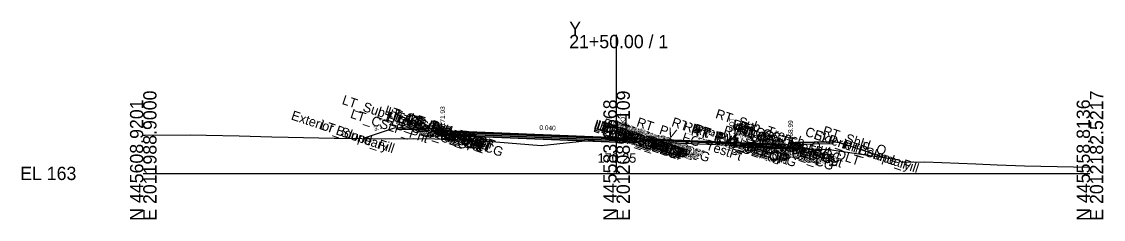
# Model space of a CAD drawing. Extents: x -26 to 3203, y -10 to 9532.
# Drawn here: x 974.3 to 1202.8, y 5490.3 to 5532 of the extents above; entities that cross this region are included whole.
import ezdxf

# ---------------------------------------------------------------- set-up
doc = ezdxf.new("R2010")
doc.units = 0
for name, color, linetype in [('Default', 7, 'Continuous'), ('Exist Cross Section Cell', 7, 'Continuous'), ('Exist XS Center Line Elevation Label', 7, 'Continuous'), ('Exist XS Ground Line', 7, 'Continuous'), ('Prop CMT Conc Surface', 7, 'Continuous'), ('Prop CMT Concrete Structures', 7, 'Continuous'), ('Prop CMT Pvmt Course 1', 7, 'Continuous'), ('Prop CMT Pvmt Course 1 CG', 7, 'Continuous'), ('Prop CMT Pvmt Course 1 Wedge', 7, 'Continuous'), ('Prop CMT Pvmt Course 2', 7, 'Continuous'), ('Prop CMT Pvmt Course 2 Wedge', 7, 'Continuous'), ('Prop CMT Pvmt Course 3', 7, 'Continuous'), ('Prop CMT Pvmt Surface', 7, 'Continuous'), ('Prop CMT Pvmt Wedge Surface 1', 7, 'Continuous'), ('Prop CMT Pvmt Wedge Surface 2', 7, 'Continuous'), ('Prop CMT Pvmt Wedge Surface 3', 7, 'Continuous'), ('Prop CMT Slope Grass', 7, 'Continuous'), ('Prop CMT Subgrade Earthwork', 7, 'Continuous'), ('Prop XS Hydro Elevations', 7, 'Continuous'), ('Prop XS Label Text', 7, 'Continuous'), ('Prop XS SE Text', 7, 'Continuous'), ('Prop XS Side Slope Text', 7, 'Continuous'), ('Scratch_Level_0', 7, 'Continuous')]:
    doc.layers.add(name, color=color, linetype=linetype)

msp = doc.modelspace()

# ---------------------------------------------------------------- linework, layer by layer
at = {"layer": 'Exist Cross Section Cell'}
for p, q in [((1100, 5500), (1100, 5529.22)), ((1000, 5500), (1100, 5500)), ((1100, 5500), (1200, 5500))]:
    msp.add_line(p, q, dxfattribs=at)
at = {"layer": 'Exist XS Ground Line'}
msp.add_lwpolyline([(1000, 5508.07), (1000.38, 5508.07), (1009.93, 5508.16), (1013.26, 5508.09), (1020.26, 5507.92), (1027.2, 5507.72), (1030.59, 5507.63), (1040.3, 5507.46), (1041.13, 5507.45), (1051.25, 5507.26), (1057.2, 5507.34), (1061.58, 5507.26), (1065.87, 5507.05), (1074.48, 5506.64), (1084.06, 5505.91), (1095.34, 5507.05), (1100, 5507.25), (1100.5, 5507.27), (1100.92, 5507.26), (1101.44, 5507.25), (1101.95, 5507.23), (1104.24, 5507.15), (1105.29, 5507.11), (1106.54, 5507.07), (1106.99, 5507.06), (1109.12, 5506.97), (1110.46, 5506.91), (1111.69, 5506.85), (1112.71, 5506.81), (1113.33, 5506.79), (1114.24, 5506.74), (1115.2, 5506.71), (1116.5, 5506.66), (1116.83, 5506.64), (1117.39, 5506.62), (1119.4, 5506.53), (1120.87, 5506.45), (1121.99, 5506.4), (1124.64, 5506.26), (1124.95, 5506.25), (1126.13, 5506.17), (1132.72, 5505.52), (1136.51, 5505.3), (1145.01, 5505.01), (1159.73, 5502.89), (1160.16, 5502.4), (1165.09, 5502.43), (1175.9, 5502.03), (1180.39, 5501.84), (1186.15, 5501.57), (1200, 5501.34)], dxfattribs=at)
at = {"layer": 'Prop CMT Conc Surface'}
for points in [[(1058.75, 5509.52), (1053.75, 5509.62)], [(1063.25, 5508.93), (1063.25, 5509.43), (1062.75, 5509.43)], [(1065.25, 5508.93), (1063.25, 5508.93)], [(1134.75, 5506.15), (1136.75, 5505.99)], [(1136.75, 5505.99), (1136.75, 5506.49), (1137.25, 5506.49)]]:
    msp.add_lwpolyline(points, dxfattribs=at)
at = {"layer": 'Prop CMT Concrete Structures'}
for points in [[(1053.75, 5509.28), (1053.75, 5509.62)], [(1053.75, 5509.62), (1058.75, 5509.52)], [(1058.75, 5509.18), (1053.75, 5509.28)], [(1058.75, 5509.52), (1058.75, 5509.18)], [(1065.25, 5508.93), (1063.25, 5508.93), (1063.25, 5509.43), (1062.75, 5509.43)], [(1062.75, 5509.43), (1062.75, 5508.44), (1065.25, 5508.34)], [(1065.25, 5508.34), (1065.25, 5508.93)], [(1108.5, 5507.2), (1108.49, 5507.36), (1107.74, 5507.61), (1107, 5507.75), (1106.26, 5507.73), (1105.51, 5507.48), (1105.5, 5507.32)], [(1105.5, 5507.32), (1108.5, 5507.2)], [(1134.75, 5506.15), (1136.75, 5505.99), (1136.75, 5506.49), (1137.25, 5506.49)], [(1137.25, 5506.49), (1137.25, 5505.46), (1134.75, 5505.56)], [(1134.75, 5505.56), (1134.75, 5506.15)], [(1145.75, 5506.67), (1137.75, 5506.51)], [(1137.75, 5506.51), (1137.75, 5506.17)], [(1137.75, 5506.17), (1145.75, 5506.33)], [(1145.75, 5506.33), (1145.75, 5506.67)]]:
    msp.add_lwpolyline(points, dxfattribs=at)
at = {"layer": 'Prop CMT Pvmt Course 1'}
for points in [[(1105.5, 5507.32), (1065.25, 5508.93)], [(1065.25, 5508.93), (1065.25, 5508.68)], [(1065.25, 5508.68), (1101.95, 5507.21)], [(1101.95, 5507.21), (1101.95, 5507.46)], [(1101.95, 5507.21), (1101.95, 5507.46)], [(1105.5, 5507.32), (1108.5, 5507.2)], [(1105.5, 5507.07), (1105.5, 5507.32)], [(1105.5, 5507.07), (1105.5, 5507.32)], [(1108.5, 5507.2), (1108.5, 5506.95)], [(1108.5, 5507.2), (1134.75, 5506.15)], [(1108.5, 5506.95), (1108.5, 5507.2)], [(1124.95, 5506.41), (1108.5, 5507.07)], [(1108.5, 5507.07), (1108.5, 5506.95), (1108.5, 5506.95)], [(1124.95, 5506.29), (1124.95, 5506.41)], [(1134.75, 5505.9), (1126.13, 5506.24)], [(1134.75, 5506.15), (1134.75, 5505.9)]]:
    msp.add_lwpolyline(points, dxfattribs=at)
for points in [[(1101.95, 5507.21), (1101.95, 5507.33), (1101.95, 5507.33), (1101.95, 5507.21)], [(1105.5, 5507.07), (1105.5, 5507.19), (1105.5, 5507.19), (1105.5, 5507.07)]]:
    msp.add_lwpolyline(points, close=True, dxfattribs=at)
at = {"layer": 'Prop CMT Pvmt Course 1 CG'}
for points in [[(1065.25, 5508.34), (1062.25, 5508.46), (1061.93, 5508.14)], [(1061.93, 5508.14), (1065.25, 5508.01)], [(1065.25, 5508.01), (1065.25, 5508.34)], [(1134.75, 5505.56), (1137.75, 5505.44), (1138.1, 5505.1)], [(1134.75, 5505.23), (1134.75, 5505.56)], [(1138.1, 5505.1), (1134.75, 5505.23)]]:
    msp.add_lwpolyline(points, dxfattribs=at)
at = {"layer": 'Prop CMT Pvmt Course 1 Wedge'}
for points in [[(1108.5, 5506.99), (1108.5, 5507.07)], [(1108.5, 5507.07), (1109.12, 5507.05), (1110.46, 5506.99), (1111.69, 5506.94), (1112.71, 5506.9), (1113.33, 5506.88), (1114.06, 5506.85), (1114.24, 5506.84), (1115.2, 5506.8), (1116.5, 5506.75), (1116.83, 5506.74), (1117.39, 5506.71), (1119.4, 5506.63), (1120.87, 5506.58), (1121.99, 5506.53), (1124.36, 5506.44), (1124.58, 5506.43), (1124.64, 5506.43), (1124.95, 5506.41)], [(1124.95, 5506.29), (1124.64, 5506.3), (1124.58, 5506.3), (1124.36, 5506.31), (1121.99, 5506.41), (1121.11, 5506.44), (1120.87, 5506.45), (1119.4, 5506.53), (1117.39, 5506.62), (1116.83, 5506.64), (1116.5, 5506.66), (1115.2, 5506.71), (1114.24, 5506.74), (1114.06, 5506.75), (1113.33, 5506.79), (1112.71, 5506.81), (1111.69, 5506.85), (1110.46, 5506.91), (1109.12, 5506.97), (1108.5, 5506.99)], [(1124.95, 5506.41), (1124.95, 5506.29), (1124.95, 5506.29)]]:
    msp.add_lwpolyline(points, dxfattribs=at)
at = {"layer": 'Prop CMT Pvmt Course 2'}
for points in [[(1101.95, 5507.21), (1065.25, 5508.68)], [(1065.25, 5508.68), (1065.25, 5508.34)], [(1065.25, 5508.34), (1101.95, 5506.87)], [(1101.95, 5506.87), (1101.95, 5507.21)], [(1101.95, 5506.87), (1101.95, 5507.21)], [(1124.95, 5505.95), (1124.95, 5506.29)], [(1124.95, 5506.29), (1134.75, 5505.9)], [(1134.75, 5505.56), (1126.13, 5505.91)], [(1134.75, 5505.9), (1134.75, 5505.56)]]:
    msp.add_lwpolyline(points, dxfattribs=at)
at = {"layer": 'Prop CMT Pvmt Course 2 Wedge'}
for points in [[(1126.13, 5506.17), (1125.97, 5506.18), (1125.07, 5506.24), (1124.95, 5506.25), (1124.64, 5506.26), (1124.58, 5506.26), (1124.36, 5506.27), (1121.99, 5506.4), (1121.11, 5506.44)], [(1121.11, 5506.44), (1121.99, 5506.41)], [(1121.99, 5506.41), (1124.36, 5506.31), (1124.58, 5506.3), (1124.64, 5506.3), (1124.95, 5506.29)], [(1124.95, 5506.29), (1124.95, 5506.22), (1124.95, 5506.22)]]:
    msp.add_lwpolyline(points, dxfattribs=at)
at = {"layer": 'Prop CMT Pvmt Course 3'}
for points in [[(1101.95, 5506.87), (1065.25, 5508.34)], [(1065.25, 5508.34), (1065.25, 5508.01)], [(1065.25, 5508.01), (1101.95, 5506.54)], [(1101.95, 5506.54), (1101.95, 5506.87)], [(1101.95, 5506.54), (1101.95, 5506.87)], [(1124.95, 5505.95), (1134.75, 5505.56)], [(1124.95, 5505.62), (1124.95, 5505.95)], [(1134.75, 5505.23), (1124.95, 5505.62)], [(1134.75, 5505.56), (1134.75, 5505.23)]]:
    msp.add_lwpolyline(points, dxfattribs=at)
at = {"layer": 'Prop CMT Pvmt Surface'}
for points in [[(1105.5, 5507.32), (1065.25, 5508.93)], [(1105.5, 5507.32), (1108.5, 5507.2)], [(1108.5, 5507.2), (1134.75, 5506.15)]]:
    msp.add_lwpolyline(points, dxfattribs=at)
at = {"layer": 'Prop CMT Pvmt Wedge Surface 1'}
for points in [[(1108.5, 5507.2), (1108.5, 5506.95), (1108.5, 5506.95), (1108.5, 5507.07)], [(1108.5, 5507.07), (1124.95, 5506.41)], [(1124.95, 5506.41), (1124.95, 5506.29)], [(1126.13, 5506.24), (1134.75, 5505.9)], [(1134.75, 5505.9), (1134.75, 5506.15)]]:
    msp.add_lwpolyline(points, dxfattribs=at)
at = {"layer": 'Prop CMT Pvmt Wedge Surface 2'}
for points in [[(1101.95, 5507.21), (1134.75, 5505.9)], [(1108.5, 5507.2), (1108.5, 5506.95)], [(1134.75, 5505.9), (1134.75, 5506.15)]]:
    msp.add_lwpolyline(points, dxfattribs=at)
at = {"layer": 'Prop CMT Pvmt Wedge Surface 3'}
for points in [[(1101.95, 5506.87), (1134.75, 5505.56)], [(1134.75, 5505.56), (1134.75, 5506.15)]]:
    msp.add_lwpolyline(points, dxfattribs=at)
at = {"layer": 'Prop CMT Slope Grass'}
for points in [[(1062.75, 5509.43), (1053.25, 5509.62), (1046.46, 5507.35)], [(1137.25, 5506.49), (1146.75, 5506.68)], [(1146.75, 5506.68), (1156.87, 5503.3)]]:
    msp.add_lwpolyline(points, dxfattribs=at)
at = {"layer": 'Prop CMT Subgrade Earthwork'}
for points in [[(1065.25, 5508.01), (1061.93, 5508.14), (1060.6, 5509.47)], [(1101.95, 5506.54), (1065.25, 5508.01)], [(1101.95, 5506.54), (1101.95, 5507.23)], [(1124.95, 5505.62), (1124.93, 5506.25)], [(1124.95, 5505.62), (1134.75, 5505.23)], [(1134.75, 5505.23), (1138.1, 5505.1), (1139.53, 5506.53)]]:
    msp.add_lwpolyline(points, dxfattribs=at)
at = {"layer": 'Prop XS Label Text'}
for p, q in [((1101.95, 5512.23), (1101.95, 5507.23)), ((1124.95, 5511.25), (1124.95, 5506.25))]:
    msp.add_line(p, q, dxfattribs=at)

# ---------------------------------------------------------------- texts
at = {"layer": 'Default'}
msp.add_text('-', height=0.0001, dxfattribs=at).set_placement((1000, 5500))
at = {"layer": 'Exist Cross Section Cell'}
for s, p in [('Y', (1090, 5529.22)), ('21+50.00 / 1', (1090, 5526.42)), ('EL 163', (974, 5498.6))]:
    msp.add_text(s, height=2.8, dxfattribs=at).set_placement(p)
for s, p in [('E 2011988.9000', (1002.8, 5490)), ('E 2012085.7109', (1102.8, 5490)), ('E 2012182.5217', (1202.8, 5490)), ('N 445608.9201', (1000, 5490)), ('N 445583.8668', (1100, 5490)), ('N 445558.8136', (1200, 5490))]:
    msp.add_text(s, height=2.8, rotation=90, dxfattribs=at).set_placement(p)
at = {"layer": 'Exist XS Center Line Elevation Label'}
msp.add_text('170.25', height=2, dxfattribs=at).set_placement((1095.98, 5502.25))
at = {"layer": 'Prop XS Hydro Elevations'}
for s, p in [('171.93', (1063.75, 5509.93)), ('168.99', (1137.25, 5506.99))]:
    msp.add_text(s, height=1, rotation=90, dxfattribs=at).set_placement(p)
at = {"layer": 'Prop XS Label Text'}
for p in [(1101.85, 5508.26), (1124.85, 5507.27)]:
    msp.add_text('E. EOT', height=1, rotation=90, dxfattribs=at).set_placement(p)
at = {"layer": 'Prop XS SE Text'}
for p in [(1083.67, 5509.19), (1119.92, 5507.74)]:
    msp.add_text('0.040', height=1, rotation=357.7094, dxfattribs=at).set_placement(p)
at = {"layer": 'Prop XS Side Slope Text'}
for rotation, p in [(18.4349, (1048.86, 5508.94)), (341.5651, (1151.62, 5505.84))]:
    msp.add_text('3:1', height=1, rotation=rotation, dxfattribs=at).set_placement(p)
at = {"layer": 'Scratch_Level_0'}
for s, p in [('LT_Sub_Trench_Out_DLT', (1041.85, 5514.67)), ('Exterior Boundary', (1031.1, 5511.42)), ('LT_CSLP_Pnt', (1043.61, 5511.77)), ('LT_CG1_Shelf_Out', (1049.18, 5511.77)), ('LT_CG_Top_Face', (1050.85, 5512.51)), ('LT_CG_Top_BOC', (1051.32, 5512.18)), ('LT_CG_Bot_BOC', (1051.35, 5511.19)), ('LT_CG_Top_Gut', (1051.77, 5511.7)), ('LT_Sub_OEOT_CG', (1052.95, 5511.05)), ('LT_CG_Bot_IE', (1055.36, 5510.58)), ('LT_PV2_OEOT', (1055.61, 5510.83)), ('LT_PV3_OEOT', (1055.61, 5510.5)), ('LT_PV1_OEOT', (1056.15, 5510.91)), ('RT_Sub_Trench_Out_DLT', (1120.74, 5511.74)), ('LT_Slope_Fill', (1037.15, 5509.4)), ('LT_Sub_OEOP', (1052.23, 5510.32)), ('LT_Sub_OEOT', (1055.52, 5510.2)), ('LT_Sub_OEEOP', (1094.95, 5508.86)), ('LT_PV2_OEEOP', (1095.04, 5509.5)), ('LT_PV3_OEEOP', (1095.04, 5509.17)), ('LT_PV1_OEEOP', (1095.58, 5509.44)), ('LT_PV2_IEEOP', (1095.65, 5509.29)), ('LT_PV1_IEEOP', (1096.19, 5509.24)), ('LT_PV2_PGL1', (1096.53, 5509)), ('LT_PV3_PGL1', (1096.53, 5508.67)), ('LT_PV2_PGL', (1096.85, 5508.9)), ('LT_PV4_PGL', (1096.85, 5508.23)), ('RT_PV_IEEOP_EG', (1096.93, 5509.79)), ('LT_PV1_PGL', (1097.39, 5508.97)), ('MI_Face In', (1097.5, 5509.1)), ('RT_PV2_IEEOP', (1098.61, 5509.19)), ('RT_PV3_IEEOP', (1098.61, 5508.86)), ('MI_Face Out', (1098.94, 5509.49)), ('MI_Top Out', (1099.1, 5509.44)), ('RT_PV1_IEEOP', (1099.15, 5509.13)), ('MI_Top In', (1099.16, 5509.04)), ('RT_PV2_PGL1', (1099.49, 5508.9)), ('RT_PV3_PGL1', (1099.49, 5508.56)), ('RT_PV2_PGL', (1099.8, 5508.79)), ('RT_PV3_PGL', (1099.8, 5508.46)), ('RT_PV4_PGL', (1099.8, 5508.12)), ('MI_Bot Out', (1099.89, 5509.01)), ('MI_Crown', (1100.11, 5508.99)), ('RT_PV1_PGL', (1100.34, 5508.86)), ('RT_PV_EG_TestPt', (1104.06, 5509.99)), ('RT_PV_Sub_Tie_Out', (1111.47, 5510)), ('RT_PV_OEEOP_EG', (1113.95, 5509.18)), ('RT_PV2_OEEOP', (1115.62, 5508.69)), ('RT_PV3_OEEOP', (1115.62, 5508.35)), ('RT_PV1_OEEOP', (1116.16, 5508.63)), ('RT_Sub_OEOT_CG', (1122.41, 5508.29)), ('RT_CG_Top_Face', (1124.3, 5509.58)), ('RT_CG1_Shelf_Out', (1124.63, 5508.76)), ('RT_CG_Top_Gut', (1125.23, 5508.77)), ('RT_PV1_OEOT', (1125.6, 5508.14)), ('RT_CG_Top_BOC', (1125.77, 5509.26)), ('RT_CG_Bot_BOC', (1125.8, 5508.22)), ('RT_Shld_O', (1143.35, 5508.17)), ('RT_Sub_OEEOP', (1115.53, 5508.05)), ('RT_CG_Bot_IE', (1124.82, 5507.82)), ('RT_Sub_OEOT', (1124.98, 5507.43)), ('RT_PV2_OEOT', (1125.07, 5508.07)), ('RT_PV3_OEOT', (1125.07, 5507.74)), ('RT_Sub_OEOP', (1128.35, 5507.29)), ('CSLP_Pnt', (1139.67, 5507.98)), ('Exterior Boundary', (1141.51, 5507.37)), ('RT_Slope_Fill', (1147.52, 5505.37))]:
    msp.add_text(s, height=2, rotation=341.5651, dxfattribs=at).set_placement(p)

doc.saveas('drawing.dxf')
